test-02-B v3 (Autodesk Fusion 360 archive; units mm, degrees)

design "test-02-B" references "test-02"
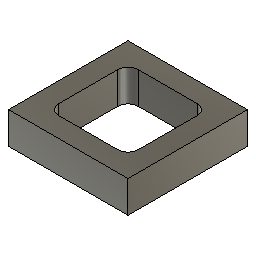
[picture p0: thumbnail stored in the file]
sketch "Sketch1" plane through (0, 0, 0) normal (0, 0, 1) x axis (1, 0, 0)
  line L1 (-75, 0) -> (0, 0)
  line L2 (-75, 75) -> (-75, 0)
  line L3 (0, 75) -> (-75, 75)
  line L4 (0, 0) -> (0, 75)
  point P1 (0, 0)
  point P2 (0, 0)
  point P3 (-75, 0)
  point P5 (0, 75)
  horizontal L1
  vertical L2
  horizontal L3
  vertical L4
  coincident P1 P2
  dimension "d1" distance P2 P3 = 75
  dimension "d2" distance P2 P5 = 75
extrude "Extrude1" new body sketch "Sketch1" along normal blind 20
component_insert "Component Insert"
joint "Assemble1" alignAngle 0 alignOffsetX 0 alignOffsetY 0 alignOffsetZ -20
combine "Combine1"
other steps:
joint_origin "JointOrigin1"

design "test-02"
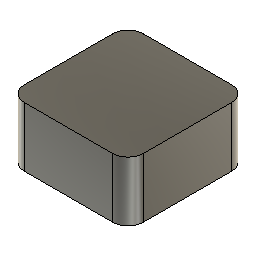
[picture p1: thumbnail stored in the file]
sketch "Sketch1" plane through (0, 0, 0) normal (0, 0, 1) x axis (1, 0, 0)
  line L1 (-50, 0) -> (0, 0)
  line L2 (-50, 50) -> (-50, 0)
  line L3 (0, 50) -> (-50, 50)
  line L4 (0, 0) -> (0, 50)
  point P1 (0, 0)
  point P2 (0, 0)
  point P3 (-50, 0)
  point P5 (0, 50)
  horizontal L1
  vertical L2
  horizontal L3
  vertical L4
  coincident P1 P2
  dimension "d1" distance P2 P3 = 50
  dimension "d2" distance P2 P5 = 50
extrude "Extrude1" new body sketch "Sketch1" along normal blind 25
fillet "Fillet1" radius 6.5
